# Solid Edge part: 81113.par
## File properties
Title: cylindrical roller thrust bearing 81113
Author: TraceParts S.A.
Template: Iso Metric Part.par
Last saved by: Nimesh.N
Revision: 9
Application: TraceParts
Company: TraceParts S.A.
Density: 7800.000 kg/m^3
Accuracy: 0.990
REFERENCE: 81113
SUPPLIER: STC-STEYR Wälzlager Deutschland GmbH
DESIGN: cylindrical roller thrust bearing 81113
TraceParts.PartNumber: 90-17062021-065719
TraceParts.PartTitle: cylindrical roller thrust bearing
TraceParts.InstanceId: 90-17062021-0657192IUWC73YMWZA9SFVBIAUEKURH
TRACEPARTS: TRACEPARTS
TraceParts.PartLanguage: en
TraceParts.PartVersion: 1.0.5
Username: Nimesh.N
Material: Steel - Free Cutting:1.0764 , 36SMn14
Face Style: Steel
Fill Style: ANSI32(Steel)
Grouping: Steel\Steel - Free Cutting ( Higher P or S content)
LibraryName: Materials-DIN
Coef. of Thermal Exp: 1.1e-05
Thermal Conductivity: 14.0
Specific Heat: 440.0
Modulus of Elasticity: 210000003072.0
Poisson's Ratio: 0.28
Yield Stress: 420000000.0
Ultimate Stress: 670000000.0
Elongation: 0.0
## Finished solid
Body 1: solid body, 3 faces, 2 edges, 2 vertices.
  Faces by surface: plane 2, cylinder 1
  Edges by curve: circle 2
Body 2: solid body, 7 faces, 7 edges, 7 vertices.
  Faces by surface: cone 2, cylinder 2, plane 2, torus 1
  Edges by curve: circle 7
Body 3: solid body, 3 faces, 2 edges, 2 vertices.
  Faces by surface: plane 2, cylinder 1
  Edges by curve: circle 2
Body 4: solid body, 3 faces, 2 edges, 2 vertices.
  Faces by surface: plane 2, cylinder 1
  Edges by curve: circle 2
Body 5: solid body, 3 faces, 2 edges, 2 vertices.
  Faces by surface: plane 2, cylinder 1
  Edges by curve: circle 2
Body 6: solid body, 3 faces, 2 edges, 2 vertices.
  Faces by surface: plane 2, cylinder 1
  Edges by curve: circle 2
Body 7: solid body, 3 faces, 2 edges, 2 vertices.
  Faces by surface: plane 2, cylinder 1
  Edges by curve: circle 2
Body 8: solid body, 3 faces, 2 edges, 2 vertices.
  Faces by surface: plane 2, cylinder 1
  Edges by curve: circle 2
Body 9: solid body, 3 faces, 2 edges, 2 vertices.
  Faces by surface: plane 2, cylinder 1
  Edges by curve: circle 2
Body 10: solid body, 3 faces, 2 edges, 2 vertices.
  Faces by surface: plane 2, cylinder 1
  Edges by curve: circle 2
Body 11: solid body, 3 faces, 2 edges, 2 vertices.
  Faces by surface: plane 2, cylinder 1
  Edges by curve: circle 2
Body 12: solid body, 3 faces, 2 edges, 2 vertices.
  Faces by surface: plane 2, cylinder 1
  Edges by curve: circle 2
Body 13: solid body, 3 faces, 2 edges, 2 vertices.
  Faces by surface: plane 2, cylinder 1
  Edges by curve: circle 2
Body 14: solid body, 3 faces, 2 edges, 2 vertices.
  Faces by surface: plane 2, cylinder 1
  Edges by curve: circle 2
Body 15: solid body, 3 faces, 2 edges, 2 vertices.
  Faces by surface: plane 2, cylinder 1
  Edges by curve: circle 2
Body 16: solid body, 3 faces, 2 edges, 2 vertices.
  Faces by surface: plane 2, cylinder 1
  Edges by curve: circle 2
Body 17: solid body, 3 faces, 2 edges, 2 vertices.
  Faces by surface: plane 2, cylinder 1
  Edges by curve: circle 2
Body 18: solid body, 3 faces, 2 edges, 2 vertices.
  Faces by surface: plane 2, cylinder 1
  Edges by curve: circle 2
Body 19: solid body, 3 faces, 2 edges, 2 vertices.
  Faces by surface: plane 2, cylinder 1
  Edges by curve: circle 2
Body 20: solid body, 3 faces, 2 edges, 2 vertices.
  Faces by surface: plane 2, cylinder 1
  Edges by curve: circle 2
Body 21: solid body, 3 faces, 2 edges, 2 vertices.
  Faces by surface: plane 2, cylinder 1
  Edges by curve: circle 2
Body 22: solid body, 3 faces, 2 edges, 2 vertices.
  Faces by surface: plane 2, cylinder 1
  Edges by curve: circle 2
Body 23: solid body, 3 faces, 2 edges, 2 vertices.
  Faces by surface: plane 2, cylinder 1
  Edges by curve: circle 2
Body 24: solid body, 3 faces, 2 edges, 2 vertices.
  Faces by surface: plane 2, cylinder 1
  Edges by curve: circle 2
Body 25: solid body, 3 faces, 2 edges, 2 vertices.
  Faces by surface: plane 2, cylinder 1
  Edges by curve: circle 2
Body 26: solid body, 7 faces, 7 edges, 7 vertices.
  Faces by surface: cone 2, cylinder 2, plane 2, torus 1
  Edges by curve: circle 7
Bounding box of the edges (mm; curved faces can reach further): 90.000 x 18.000 x 90.000, from (-45, 0, -45) to (45, 18, 45).
Cylindrical faces by radius (mm): R3 x24, R32.5 x1, R33.4 x1, R44.1 x1, R45 x1
Conical faces (half-angle, radius in mm at the cone's reference point): 45 deg R32.95 x1, 45 deg R33.85 x1, 45 deg R43.65 x1, 45 deg R44.55 x1
Toroidal faces (ring radius, tube radius in mm): R43.65 r0.45 x1, R44.55 r0.45 x1
Planar faces by outward normal: +x 2, +y 2, +z 2, -x 2, -y 2, -z 2, oblique 40
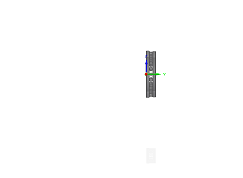
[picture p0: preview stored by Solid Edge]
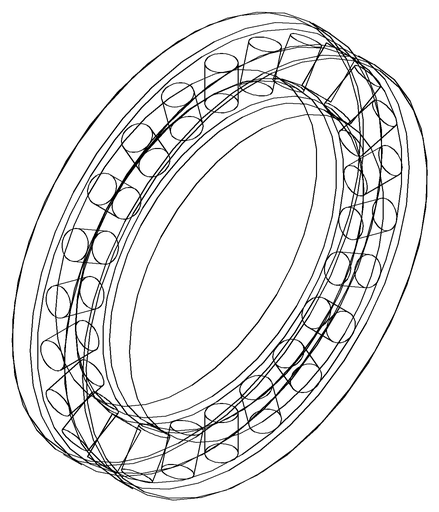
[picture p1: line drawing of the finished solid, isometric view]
